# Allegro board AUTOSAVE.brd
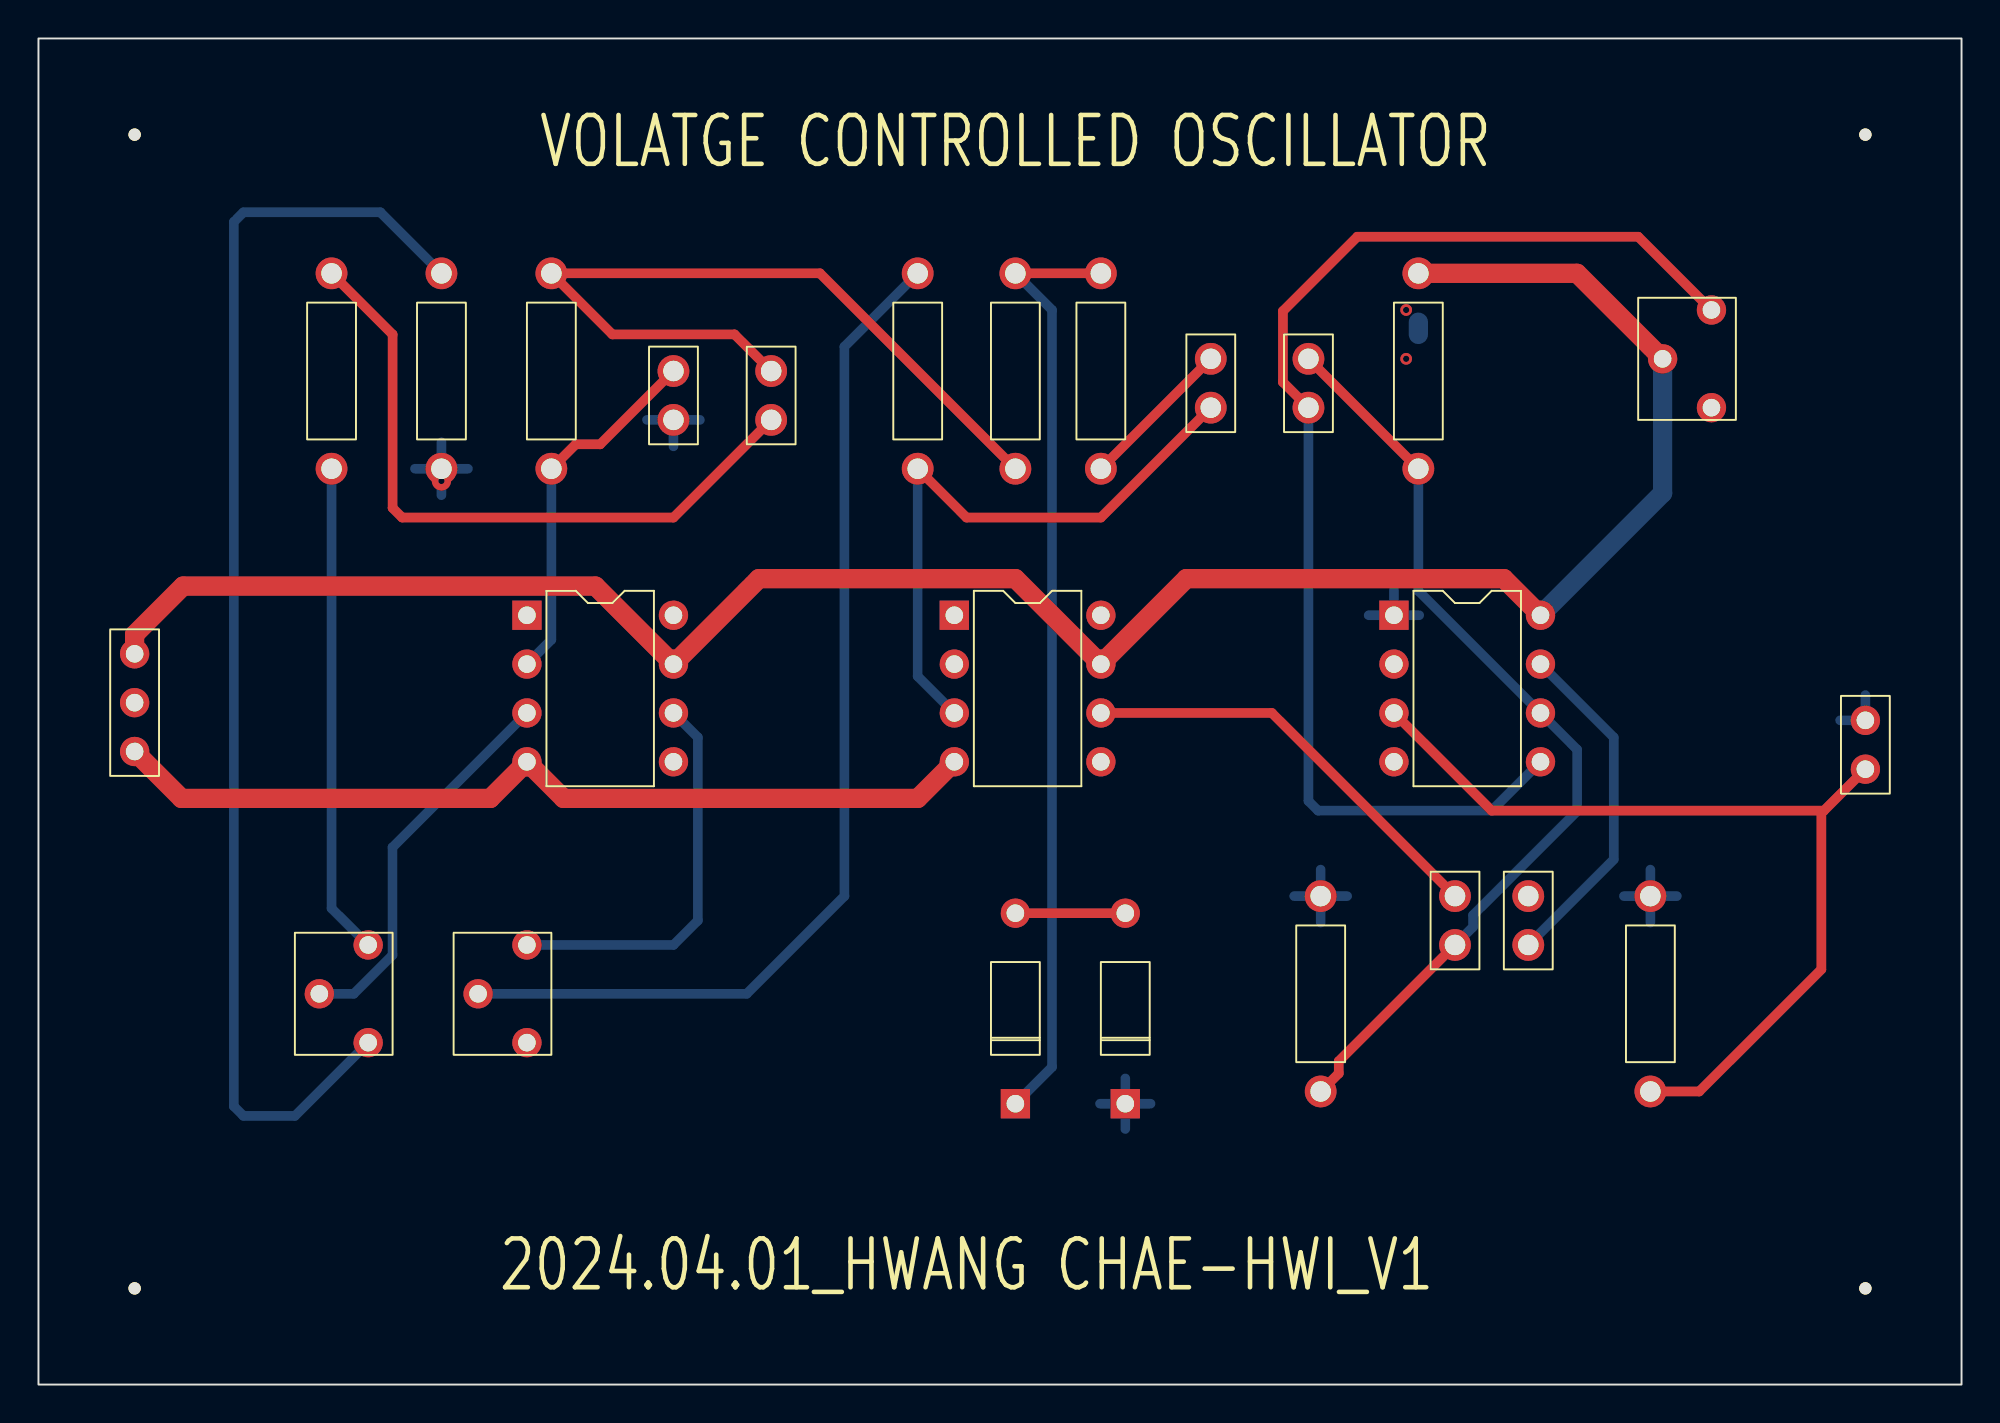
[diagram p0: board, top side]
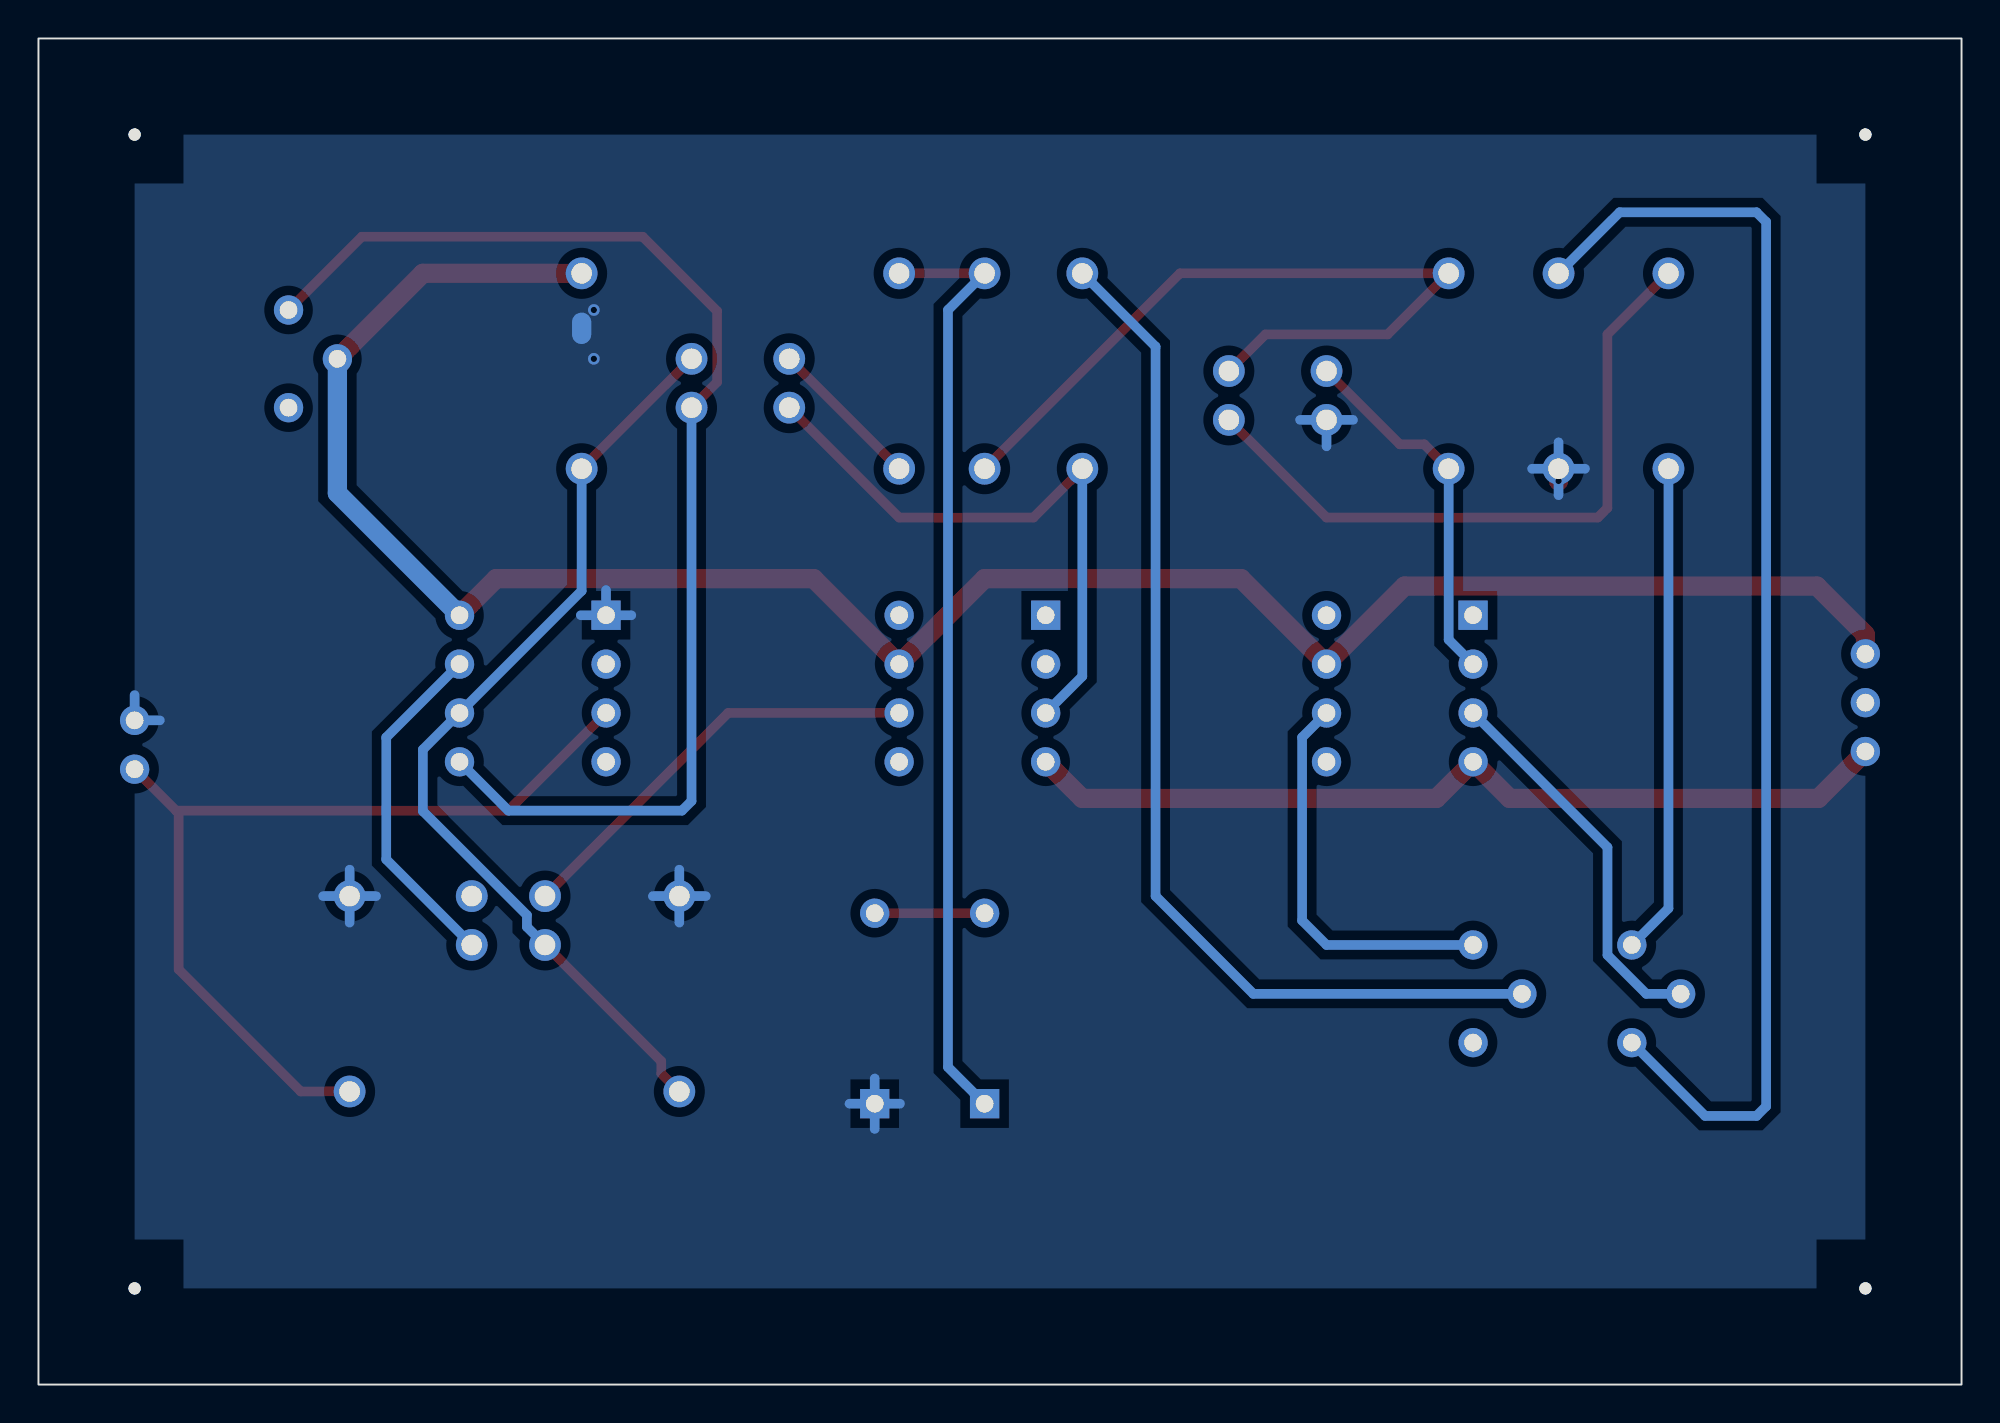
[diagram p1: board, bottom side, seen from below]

Outline 100 x 70 mm; copper layers: TOP, BOTTOM. Coordinates in mm from the lower left corner of the outline.
Outline path: rectangle 0,0 100,70

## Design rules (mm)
nets with their own width: min track width 1; nets +12V -12V GND

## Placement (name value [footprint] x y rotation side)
C1  2200pF  [CAPCK05]  60.96 50.8 0 top
C2  0.01uF  [CAPCK05]  66.04 50.8 0 top
C3  2200pF  [CAPCK05]  38.1 50.16 0 top
C4  0.1uF  [CAPCK05]  73.66 22.86 0 top
C5  0.1uF  [CAPCK05]  77.47 22.86 0 top
C6  2200pF  [CAPCK05]  33.02 50.16 0 top
D1  RD 3.9A  [DO41]  50.8 14.61 0 top
D2  RD 3.9A  [DO41]  56.52 14.61 0 top
J1  CON2  [JUMPER2]  95 32 90 top
J2  CON3  [JUMPER3]  5 38 270 top
NOREF  -  []  0 70 0 top
NOREF#2  -  [unnamed#2]  95 5 0 top
NOREF#3  -  []  5 38 90 top
NOREF#4  -  []  95 65 0 top
NOREF#5  -  []  95 5 90 top
NOREF#6  -  [unnamed#2]  5 65 0 top
NOREF#7  -  [unnamed#2]  95 65 0 top
NOREF#8  -  []  5 65 90 top
NOREF#9  -  []  0 70 0 top
NOREF#10  -  []  5 65 0 top
NOREF#11  -  []  100 0 90 top
NOREF#12  -  [unnamed#2]  5 5 0 top
NOREF#13  -  []  0 0 90 top
NOREF#14  -  []  0 0 90 top
NOREF#15  -  []  5 5 90 top
R1  4.7k  [RES400]  15.24 47.62 0 top
R2  3,3K  [RES400]  71.75 47.62 0 top
R3  10K  [RES400]  45.72 47.62 0 top
R4  1K  [RES400]  55.24 47.62 0 top
R5  8,2K  [RES400]  66.67 15.24 0 top
R6  4.7k  [RES400]  83.82 15.24 0 top
R7  12K  [RES400]  26.67 47.62 0 top
R8  12K  [RES400]  50.8 47.62 0 top
R9  10K  [RES400]  20.95 47.62 0 top
U1  LM741  [DIP8_3]  25.4 40.01 0 top
U2  LM741  [DIP8_3]  47.62 40.01 0 top
U3  LM566C  [DIP8_3]  70.48 40.01 0 top
VR1  4.7K  [RESADJ]  87 55.88 0 top
VR2  10k  [RESADJ]  17.14 22.86 0 top
VR3  2K  [RESADJ]  25.4 22.86 0 top

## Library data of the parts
C1-C6 = CAP NP: Tolerance: ***; User Part Number: ***
D1 D2 = DIODE ZENER
J1 = CON2: User Part Number: ***
J2 = CON3: User Part Number: ***
R1-R9 = R: Tolerance: ***; User Part Number: ***
U1 U2 = LM741_0: Tolerance: ***; User Part Number: ***
U3 = LM566C_3: Tolerance: ***; User Part Number: ***
VR1 VR3 = RESISTOR VAR 2: Tolerance: ***; User Part Number: ***
VR2 = RESISTOR VAR: Tolerance: ***; User Part Number: ***

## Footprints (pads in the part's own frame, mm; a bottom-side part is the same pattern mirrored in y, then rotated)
CAPCK05
  round 1.651 hole 1.067: 1(0,0) 2(0,2.54)
DIP8_3
  rect 1.524x1.524 hole 0.914: 1(0,0)
  round 1.524 hole 0.914: 2(0,-2.54) 3(0,-5.08) 4(0,-7.62) 5(7.62,-7.62) 6(7.62,-5.08) 7(7.62,-2.54) 8(7.62,0)
DO41
  rect 1.524x1.524 hole 0.914: 1(0,0)
  round 1.524 hole 0.914: 2(0,9.906)
JUMPER2
  round 1.524 hole 0.914: 1(0,0) 2(2.54,0)
JUMPER3
  round 1.524 hole 0.914: 1(0,0) 2(2.54,0) 3(5.08,0)
RES400
  round 1.651 hole 1.067: 1(0,0) 2(0,10.16)
RESADJ
  round 1.524 hole 0.914: 1(0,0) 2(-2.54,-2.54) 3(0,-5.08)
unnamed#2
  round 0.635 hole 3.175 unplated: (0,0)

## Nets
+12V: J2.1 R2.2 U1.7(V+) U2.7(V+) U3.8 VR1.2
-12V: J2.3 U1.4(V-) U2.4(V-)
GND: C5.2 C6.1 D2.1(CATHODE) J1.2 J2.2 R5.2 R6.2 R9.1 U2.2(-IN) U3.1
A1: C4.2 U2.6(OUT)
OUT: J1.1 R6.1 U3.3(SQWOUT)
N01144: R1.1 VR2.1(A)
N01158: U1.3(+IN) VR2.2(WIPER)
N01162: U1.6(OUT) VR3.1
N01166: C3.1 R1.2
N01173: C6.2 R7.1 U1.2(-IN)
N01186: R9.2 VR2.3(B)
N01206: C3.2 R7.2 R8.1
N01220: R3.2 VR3.2
N01242: C1.1 R3.1 U2.3(+IN)
N01254: C1.2 R4.1
N01261: D1.1(CATHODE) R4.2 R8.2
N01265: D1.2(ANODE) D2.2(ANODE)
N01354: C2.2 C4.1 R2.1 R5.1 U3.6(TRES)
N01358: C2.1 U3.5(MOD) VR1.1
N01436: C5.1 U3.7(TCAP)

Pads without a net: U1 1 5 8; U2 1 5 8; U3 2 4; VR1 3; VR3 3

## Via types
v1: diameter 0.61, hole 0.33, TOP to BOTTOM, 11 vias

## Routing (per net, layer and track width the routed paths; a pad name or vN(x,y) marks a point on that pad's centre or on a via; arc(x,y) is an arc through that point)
+12V: length 113.6
  TOP w1: VR1.2 80.01,57.78 R2.2 ; v1(5,38) 5,39 7.52,41.52 28.96,41.52 U1.7 37.47,41.91 50.8,41.91 U2.7 59.69,41.91 76.2,41.91 U3.8
  BOTTOM w1: U3.8 84.45,46.35 VR1.2
-12V: length 46
  TOP w1: 47.62,32.38 45.72,30.48 27.3,30.48 25.4,32.38 23.5,30.48 7.44,30.48 J2.3
GND: length 33.7
  TOP w1: v1(20.95,46.99) v1(20.95,47.62)
  BOTTOM w0.5: v1(20.95,47.62) 22.33,47.62 ; v1(20.95,47.62) 20.95,46.25 ; v1(20.95,47.62) 20.95,49 ; v1(20.95,47.62) 19.58,47.62 ; 83.82,24.02 R6.2 ; R6.2 85.2,25.4 ; R6.2 82.44,25.4 ; R6.2 83.82,26.78 ; 93.69,34.54 J1.2 95,35.85 ; U3.1 70.48,41.32 ; U3.1 71.8,40.01 ; U3.1 69.17,40.01 ; R5.2 66.67,26.78 ; R5.2 66.67,24.02 ; R5.2 68.05,25.4 ; R5.2 65.3,25.4 ; D2.1 56.52,15.92 ; D2.1 56.52,13.29 ; D2.1 55.2,14.61 ; D2.1 57.83,14.61 ; 33.02,48.79 C6.1 ; C6.1 34.4,50.16 ; C6.1 31.64,50.16
  BOTTOM w1: 71.75,55.24 71.75,54.61
  vias: v1(71.12,55.88) v1(71.12,53.34)
A1: length 22.4
  TOP w0.5: 55.24,34.92 64.14,34.92 C4.2
OUT: length 47.3
  TOP w0.5: 92.84,29.84 92.71,29.71 92.71,21.59 86.36,15.24 R6.1 ; 92.84,29.84 75.56,29.84 70.48,34.92 ; 92.84,29.84 J1.1
N01144: length 25.6
  BOTTOM w0.5: VR2.1 15.24,24.77 v1(15.24,47.62)
N01158: length 20.1
  BOTTOM w0.5: VR2.2 16.4,20.32 18.41,22.34 18.41,27.94 25.4,34.92
N01162: length 20.7
  BOTTOM w0.5: VR3.1 33.02,22.86 34.29,24.13 34.29,33.66 33.02,34.92
N01166: length 35.5
  TOP w0.5: C3.1 33.02,45.09 18.91,45.09 18.41,45.59 18.41,54.61 R1.2
N01173: length 19.1
  TOP w0.5: C6.2 29.21,48.9 27.94,48.9 R7.1
  BOTTOM w0.5: U1.2 26.67,38.73 R7.1
N01186: length 67.1
  BOTTOM w0.5: VR2.3 13.34,13.97 10.66,13.97 10.16,14.47 10.16,60.46 10.66,60.96 17.78,60.96 v1(20.95,57.78)
N01206: length 41.9
  TOP w0.5: C3.2 36.2,54.61 29.84,54.61 R7.2 40.64,57.78 R8.1
N01220: length 55.1
  BOTTOM w0.5: VR3.2 36.83,20.32 41.91,25.4 41.91,53.98 R3.2
N01242: length 32.1
  TOP w0.5: C1.1 55.24,45.09 48.26,45.09 R3.1
  BOTTOM w0.5: R3.1 45.72,36.83 47.62,34.92
N01254: length 8.1
  TOP w0.5: C1.2 R4.1
N01261: length 49.2
  TOP w0.5: R8.2 R4.2
  BOTTOM w0.5: R8.2 52.7,55.88 52.7,16.51 D1.1
N01265: length 5.7
  TOP w0.5: D2.2 D1.2
N01354: length 49.4
  TOP w0.5: C4.1 67.62,16.82 67.62,16.18 R5.1 ; C2.2 R2.1
  BOTTOM w0.5: R2.1 71.75,41.27 80.01,33.02 80.01,29.82 74.6,24.41 74.6,23.8 C4.1
N01358: length 64.8
  TOP w0.5: VR1.1 83.19,59.69 68.58,59.69 64.71,55.82 64.71,52.13 C2.1
  BOTTOM w0.5: 78.11,32.38 75.56,29.84 66.54,29.84 66.04,30.34 C2.1
N01436: length 18
  BOTTOM w0.5: U3.7 81.92,33.66 81.92,27.3 C5.1

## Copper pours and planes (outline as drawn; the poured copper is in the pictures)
GND on BOTTOM: 5,5 5,65 95,65 95,5 ; 1 cut-out

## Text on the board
Ref Des/Silkscreen Top: 2024.04.01_HWANG CHAE-HWI_V1 | VOLATGE CONTROLLED OSCILLATOR
DIMENSION: FIGURE | SIZE | 0.3302 | 0.9144 | 1.0668 | 3.175 | DRILL CHART: TOP to BOTTOM | ALL UNITS ARE IN MILLIMETERS | PLATED | NON-PLATED | QTY | 11 | 42 | 30 | 4
